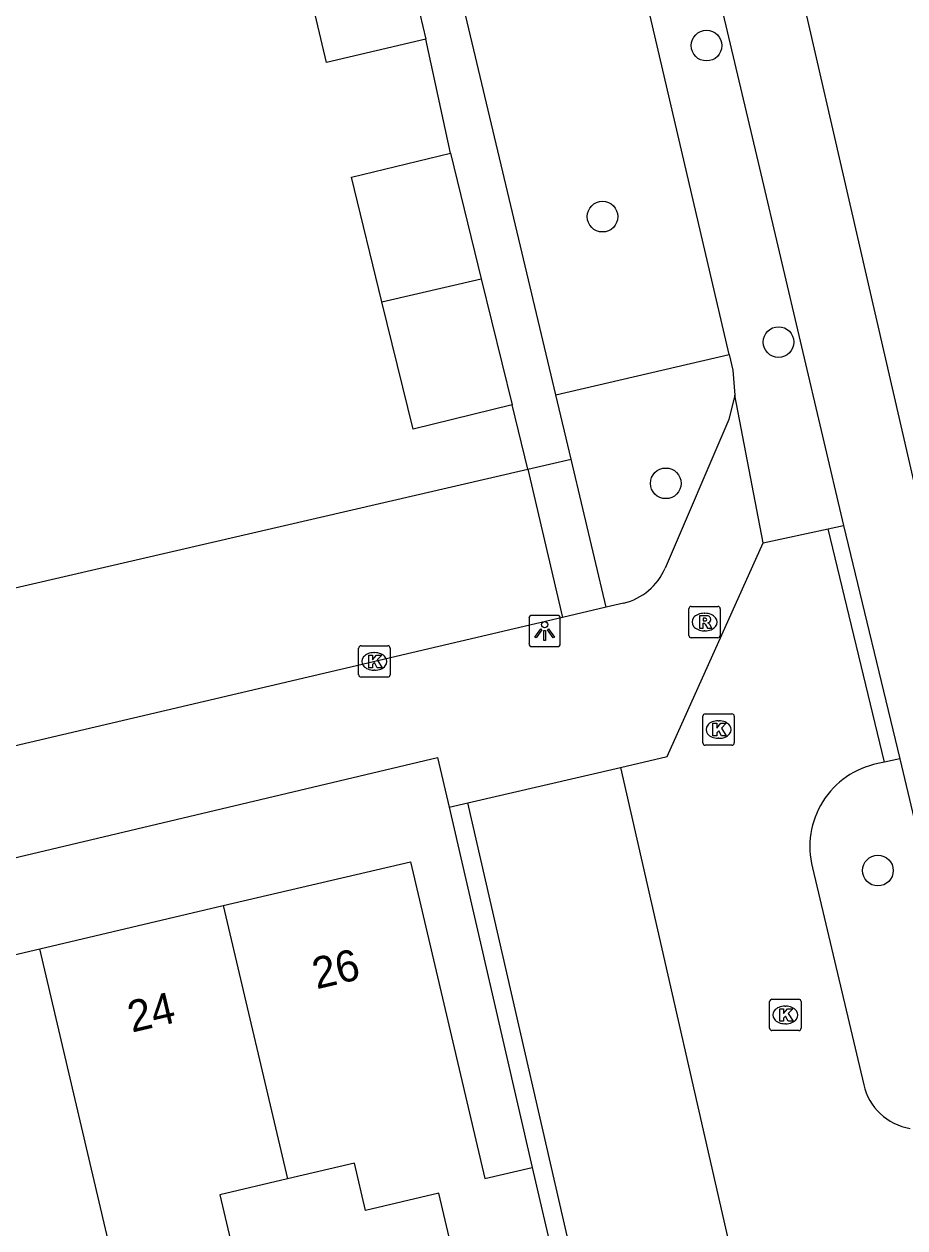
# Model space of a CAD drawing. Extents: x 158474 to 159560, y 388525 to 389605.
# Drawn here: x 159230.1 to 159258.19, y 388849.05 to 388887.46 of the extents above; entities that cross this region are included whole.
import ezdxf

# ---------------------------------------------------------------- set-up
doc = ezdxf.new("R2010")
doc.units = 0
for name, color, linetype in [('IMGEO_Berm_groen', 7, 'Continuous'), ('IMGEO_Boom', 7, 'Continuous'), ('IMGEO_Groenvoorziening', 7, 'Continuous'), ('IMGEO_Kolk', 7, 'Continuous'), ('IMGEO_Lichtpunt', 7, 'Continuous'), ('IMGEO_Muur', 7, 'Continuous'), ('IMGEO_Pand', 7, 'Continuous'), ('IMGEO_Pand_nummerreeks', 7, 'Continuous'), ('IMGEO_Rijbaan_lokaal_gesloten', 7, 'Continuous'), ('IMGEO_Rijbaan_lokaal_open', 7, 'Continuous'), ('IMGEO_Rioolput', 7, 'Continuous'), ('IMGEO_Voetpad_open', 7, 'Continuous')]:
    doc.layers.add(name, color=color, linetype=linetype)

msp = doc.modelspace()

# ---------------------------------------------------------------- linework, layer by layer
at = {"layer": 'IMGEO_Berm_groen'}
msp.add_lwpolyline([(159247.059, 388875.634), (159252.59, 388876.924)], dxfattribs=at)
at = {"layer": 'IMGEO_Boom'}
for centre in [(159251.865, 388886.774), (159248.548, 388881.317), (159254.161, 388877.316), (159250.565, 388872.808), (159257.33, 388860.453)]:
    msp.add_circle(centre, 0.489, dxfattribs=at)
at = {"layer": 'IMGEO_Groenvoorziening'}
msp.add_lwpolyline([(159222.323, 388867.736), (159246.163, 388873.265)], dxfattribs=at)
at = {"layer": 'IMGEO_Kolk'}
for p, q in [((159240.846, 388867.626), (159241.698, 388867.626)), ((159240.771, 388866.7), (159240.771, 388867.552)), ((159241.259, 388867.406), (159241.284, 388867.406)), ((159241.772, 388867.552), (159241.772, 388866.7)), ((159241.282, 388866.846), (159241.257, 388866.846)), ((159241.698, 388866.626), (159240.846, 388866.626)), ((159251.75, 388864.526), (159251.75, 388865.378)), ((159251.825, 388865.452), (159252.677, 388865.452)), ((159252.751, 388865.378), (159252.751, 388864.526)), ((159252.238, 388865.232), (159252.263, 388865.232)), ((159252.261, 388864.672), (159252.236, 388864.672)), ((159252.677, 388864.452), (159251.825, 388864.452)), ((159253.878, 388855.419), (159253.878, 388856.271)), ((159253.953, 388856.345), (159254.805, 388856.345)), ((159254.366, 388856.125), (159254.391, 388856.125)), ((159254.879, 388856.271), (159254.879, 388855.419)), ((159254.805, 388855.345), (159253.953, 388855.345)), ((159254.389, 388855.565), (159254.364, 388855.565))]:
    msp.add_line(p, q, dxfattribs=at)
for points in [[(159240.846, 388867.626), (159241.698, 388867.626)], [(159240.771, 388866.7), (159240.771, 388867.552)], [(159241.092, 388867.326), (159241.215, 388867.326), (159241.215, 388867.175), (159241.345, 388867.326), (159241.509, 388867.326), (159241.363, 388867.175), (159241.516, 388866.926), (159241.364, 388866.926), (159241.279, 388867.09), (159241.215, 388867.023), (159241.215, 388866.926), (159241.092, 388866.926), (159241.092, 388867.326)], [(159241.772, 388867.552), (159241.772, 388866.7)], [(159241.698, 388866.626), (159240.846, 388866.626)], [(159251.75, 388864.526), (159251.75, 388865.378)], [(159251.825, 388865.452), (159252.677, 388865.452)], [(159252.751, 388865.378), (159252.751, 388864.526)], [(159252.071, 388865.152), (159252.194, 388865.152), (159252.194, 388865.001), (159252.324, 388865.152), (159252.488, 388865.152), (159252.342, 388865.001), (159252.495, 388864.752), (159252.343, 388864.752), (159252.258, 388864.916), (159252.194, 388864.849), (159252.194, 388864.752), (159252.071, 388864.752), (159252.071, 388865.152)], [(159252.677, 388864.452), (159251.825, 388864.452)], [(159253.878, 388855.419), (159253.878, 388856.271)], [(159253.953, 388856.345), (159254.805, 388856.345)], [(159254.879, 388856.271), (159254.879, 388855.419)], [(159254.199, 388856.045), (159254.322, 388856.045), (159254.322, 388855.894), (159254.452, 388856.045), (159254.616, 388856.045), (159254.47, 388855.894), (159254.623, 388855.645), (159254.471, 388855.645), (159254.386, 388855.809), (159254.322, 388855.742), (159254.322, 388855.645), (159254.199, 388855.645), (159254.199, 388856.045)], [(159254.805, 388855.345), (159253.953, 388855.345)]]:
    msp.add_lwpolyline(points, dxfattribs=at)
for centre, start, end in [((159240.848, 388867.55), 91.552, 178.448), ((159240.848, 388867.55), 91.552, 178.448), ((159241.696, 388867.55), 1.552, 88.448), ((159241.696, 388867.55), 1.552, 88.448), ((159240.848, 388866.702), 181.552, 268.448), ((159240.848, 388866.702), 181.552, 268.448), ((159241.696, 388866.702), 271.552, 358.448), ((159241.696, 388866.702), 271.552, 358.448), ((159251.827, 388865.376), 91.552, 178.448), ((159251.827, 388865.376), 91.552, 178.448), ((159252.675, 388865.376), 1.552, 88.448), ((159252.675, 388865.376), 1.552, 88.448), ((159251.827, 388864.528), 181.552, 268.448), ((159251.827, 388864.528), 181.552, 268.448), ((159252.675, 388864.528), 271.552, 358.448), ((159252.675, 388864.528), 271.552, 358.448), ((159253.955, 388856.269), 91.552, 178.448), ((159253.955, 388856.269), 91.552, 178.448), ((159254.803, 388856.269), 1.552, 88.448), ((159254.803, 388856.269), 1.552, 88.448), ((159253.955, 388855.421), 181.552, 268.448), ((159253.955, 388855.421), 181.552, 268.448), ((159254.803, 388855.421), 271.552, 358.448), ((159254.803, 388855.421), 271.552, 358.448)]:
    msp.add_arc(centre, 0.0765, start, end, dxfattribs=at)
for centre, major_axis, ratio, start_param, end_param in [((159241.258, 388867.126), (-0.387, 0.002), 0.722429, 4.712389, 7.853982), ((159241.283, 388867.126), (-0.39, 0.002), 0.717154, 1.570796, 4.712389), ((159252.237, 388864.952), (-0.387, 0.002), 0.722429, 4.712389, 7.853982), ((159252.262, 388864.952), (-0.39, 0.002), 0.717154, 1.570796, 4.712389), ((159254.365, 388855.845), (-0.387, 0.002), 0.722429, 4.712389, 7.853982), ((159254.39, 388855.845), (-0.39, 0.002), 0.717154, 1.570796, 4.712389)]:
    msp.add_ellipse(centre, major_axis=major_axis, ratio=ratio, start_param=start_param, end_param=end_param, dxfattribs=at)
at = {"layer": 'IMGEO_Lichtpunt'}
for p, q in [((159246.204, 388868.501), (159246.204, 388867.694)), ((159246.204, 388868.501), (159246.204, 388867.694)), ((159247.106, 388868.596), (159246.298, 388868.596)), ((159247.106, 388868.596), (159246.298, 388868.596)), ((159247.2, 388867.694), (159247.2, 388868.501)), ((159247.2, 388867.694), (159247.2, 388868.501)), ((159246.298, 388867.6), (159247.106, 388867.6)), ((159246.298, 388867.6), (159247.106, 388867.6))]:
    msp.add_line(p, q, dxfattribs=at)
for points in [[(159246.578, 388868.165), (159246.617, 388868.137), (159246.429, 388867.875), (159246.391, 388867.902), (159246.578, 388868.165)], [(159246.68, 388868.117), (159246.727, 388868.117), (159246.727, 388867.795), (159246.68, 388867.795), (159246.68, 388868.117)], [(159246.79, 388868.137), (159246.828, 388868.164), (159247.015, 388867.902), (159246.976, 388867.874), (159246.79, 388868.137)]]:
    msp.add_lwpolyline(points, dxfattribs=at)
msp.add_circle((159246.703, 388868.299), 0.0994, dxfattribs=at)
for centre, start, end in [((159246.298, 388868.501), 90, 180), ((159246.298, 388868.501), 90, 180), ((159247.106, 388868.501), 0, 90), ((159247.106, 388868.501), 0, 90), ((159246.298, 388867.694), 180, 270), ((159246.298, 388867.694), 180, 270), ((159247.106, 388867.694), 270, 0), ((159247.106, 388867.694), 270, 360)]:
    msp.add_arc(centre, 0.0946, start, end, dxfattribs=at)
at = {"layer": 'IMGEO_Muur'}
msp.add_lwpolyline([(159246.163, 388873.265), (159247.547, 388873.581)], dxfattribs=at)
at = {"layer": 'IMGEO_Pand'}
for points in [[(159241.957, 388891.03), (159242.913, 388886.979)], [(159242.913, 388886.979), (159239.75, 388886.233), (159238.792, 388890.294)], [(159241.513, 388878.6), (159240.543, 388882.574), (159243.702, 388883.345)], [(159243.702, 388883.345), (159244.681, 388879.337)], [(159241.513, 388878.6), (159244.681, 388879.337)], [(159244.681, 388879.337), (159245.664, 388875.309)], [(159245.664, 388875.309), (159242.505, 388874.538), (159241.513, 388878.6)], [(159236.455, 388859.334), (159242.426, 388860.735), (159244.798, 388850.629), (159246.3, 388850.982)], [(159230.601, 388857.96), (159236.455, 388859.334)], [(159236.455, 388859.334), (159238.501, 388850.617)], [(159224.747, 388856.586), (159230.601, 388857.96)], [(159234.391, 388841.809), (159230.601, 388857.96)], [(159247.021, 388847.913), (159244.02, 388847.209), (159243.328, 388850.157), (159240.991, 388849.608), (159240.636, 388851.118), (159238.501, 388850.617)], [(159246.3, 388850.982), (159247.021, 388847.913)], [(159238.501, 388850.617), (159236.342, 388850.11), (159236.682, 388848.66), (159234.513, 388848.151), (159235.918, 388842.167)]]:
    msp.add_lwpolyline(points, dxfattribs=at)
at = {"layer": 'IMGEO_Rijbaan_lokaal_gesloten'}
for points in [[(159268.084, 388832.358), (159258.627, 388872.238), (159243.098, 388939.791), (159230.156, 389009.067), (159223.469, 389052.45)], [(159245.615, 388916.829), (159246.05, 388914.888), (159249.806, 388898.745), (159253.55, 388882.862), (159256.234, 388871.462)], [(159256.234, 388871.462), (159258.029, 388864.014)], [(159258.029, 388864.014), (159260.868, 388852.063)]]:
    msp.add_lwpolyline(points, dxfattribs=at)
at = {"layer": 'IMGEO_Rijbaan_lokaal_open'}
for points in [[(159253.668, 388870.909), (159255.745, 388871.357)], [(159257.54, 388863.91), (159255.745, 388871.357)], [(159249.126, 388863.743), (159250.613, 388864.087), (159253.668, 388870.909)], [(159257.54, 388863.91), (159257.328, 388863.865)], [(159249.126, 388863.743), (159253.133, 388846.145)], [(159255.247, 388860.543), (159256.879, 388853.62)]]:
    msp.add_lwpolyline(points, dxfattribs=at)
for centre, radius, start, end in [((159257.854, 388861.223), 2.694, 101.264, 194.6075), ((159258.663, 388854.027), 1.83, 192.8448, 260.3053)]:
    msp.add_arc(centre, radius, start, end, dxfattribs=at)
at = {"layer": 'IMGEO_Rioolput'}
for p, q in [((159251.302, 388867.956), (159251.302, 388868.808)), ((159251.377, 388868.882), (159252.229, 388868.882)), ((159252.303, 388868.808), (159252.303, 388867.956)), ((159251.79, 388868.662), (159251.815, 388868.662)), ((159251.813, 388868.102), (159251.788, 388868.102)), ((159252.229, 388867.882), (159251.377, 388867.882))]:
    msp.add_line(p, q, dxfattribs=at)
for points in [[(159251.302, 388867.956), (159251.302, 388868.808)], [(159251.377, 388868.882), (159252.229, 388868.882)], [(159252.303, 388868.808), (159252.303, 388867.956)], [(159251.891, 388868.58), (159251.639, 388868.582), (159251.639, 388868.182)], [(159251.817, 388868.501), (159251.763, 388868.501), (159251.763, 388868.42)], [(159251.763, 388868.42), (159251.815, 388868.42)], [(159251.639, 388868.182), (159251.763, 388868.182), (159251.763, 388868.344), (159251.774, 388868.344)], [(159251.821, 388868.315), (159251.892, 388868.182), (159252.032, 388868.182), (159251.967, 388868.308)], [(159252.229, 388867.882), (159251.377, 388867.882)]]:
    msp.add_lwpolyline(points, dxfattribs=at)
for centre, radius, start, end in [((159251.379, 388868.806), 0.0765, 91.552, 178.448), ((159251.379, 388868.806), 0.0765, 91.552, 178.448), ((159252.227, 388868.806), 0.0765, 1.552, 88.448), ((159252.227, 388868.806), 0.0765, 1.552, 88.448), ((159251.799, 388868.609), 0.19, 274.7715, 282.9687), ((159251.823, 388868.405), 0.0964, 77.0061, 93.1865), ((159251.837, 388868.462), 0.0378, 276.6634, 79.6772), ((159251.89, 388868.47), 0.109, 350.3612, 89.416), ((159251.888, 388868.47), 0.112, 277.5842, 350.9817), ((159251.872, 388868.255), 0.108, 29.5134, 73.7905), ((159251.773, 388868.291), 0.0533, 26.0293, 88.6989), ((159251.379, 388867.958), 0.0765, 181.552, 268.448), ((159251.379, 388867.958), 0.0765, 181.552, 268.448), ((159252.227, 388867.958), 0.0765, 271.552, 358.448), ((159252.227, 388867.958), 0.0765, 271.552, 358.448)]:
    msp.add_arc(centre, radius, start, end, dxfattribs=at)
for centre, major_axis, ratio, start_param, end_param in [((159251.789, 388868.382), (-0.387, 0.002), 0.722429, 4.712389, 7.853982), ((159251.814, 388868.382), (-0.39, 0.002), 0.717154, 1.570796, 4.712389)]:
    msp.add_ellipse(centre, major_axis=major_axis, ratio=ratio, start_param=start_param, end_param=end_param, dxfattribs=at)
at = {"layer": 'IMGEO_Voetpad_open'}
for points in [[(159252.59, 388876.924), (159243.425, 388916.225), (159243.383, 388916.406), (159243.158, 388916.349), (159241.466, 388915.922)], [(159247.059, 388875.634), (159237.713, 388914.975), (159241.466, 388915.922)], [(159243.702, 388883.345), (159242.913, 388886.979)], [(159252.59, 388876.924), (159252.708, 388876.418), (159252.767, 388875.619)], [(159246.163, 388873.265), (159245.664, 388875.309)], [(159248.669, 388868.858), (159247.547, 388873.581), (159247.059, 388875.634)], [(159252.767, 388875.619), (159252.572, 388874.841), (159250.545, 388870.1)], [(159253.668, 388870.909), (159252.767, 388875.619)], [(159246.163, 388873.265), (159247.274, 388868.53)], [(159255.745, 388871.357), (159256.234, 388871.462)], [(159248.669, 388868.858), (159247.274, 388868.53)], [(159249.22, 388868.987), (159248.669, 388868.858)], [(159247.274, 388868.53), (159242.463, 388867.4), (159206.766, 388859.019)], [(159198.829, 388853.512), (159243.288, 388864.061), (159243.653, 388862.478)], [(159258.029, 388864.014), (159257.54, 388863.91)], [(159244.254, 388862.616), (159249.126, 388863.743)], [(159243.653, 388862.478), (159244.254, 388862.616)], [(159253.133, 388846.145), (159248.287, 388845.046), (159244.254, 388862.616)], [(159243.653, 388862.478), (159246.3, 388850.982)]]:
    msp.add_lwpolyline(points, dxfattribs=at)
msp.add_arc((159248.784, 388870.852), 1.915, 283.1721, 336.8884, dxfattribs=at)

# ---------------------------------------------------------------- texts
at = {"layer": 'IMGEO_Pand_nummerreeks'}
for s, p in [('26', (159239.427, 388856.662)), ('24', (159233.539, 388855.28))]:
    msp.add_text(s, height=1, rotation=13.2074, dxfattribs=at).set_placement(p)

doc.saveas('drawing.dxf')
